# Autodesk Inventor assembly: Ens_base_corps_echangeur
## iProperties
Shininess: 64.0
Length Units: 11269
Angle Units: 11279
Time Units: 11290
Mass Units: 11283
Length Display Precision: 3
Angle Display Precision: 2
Compacted: True
Created: 2008-02
Part Number: Ens_base_corps_echangeur
Document SubType Name: Assembly
Designer: Pascal
Density: 0.0
Volumn: 0.0
Area: 0.0
PropertySet Name: Model Information
Control State: 0
Master: False
Checked Out: False
DESIGNATION: Base corps échangeur
Author: Pascal
